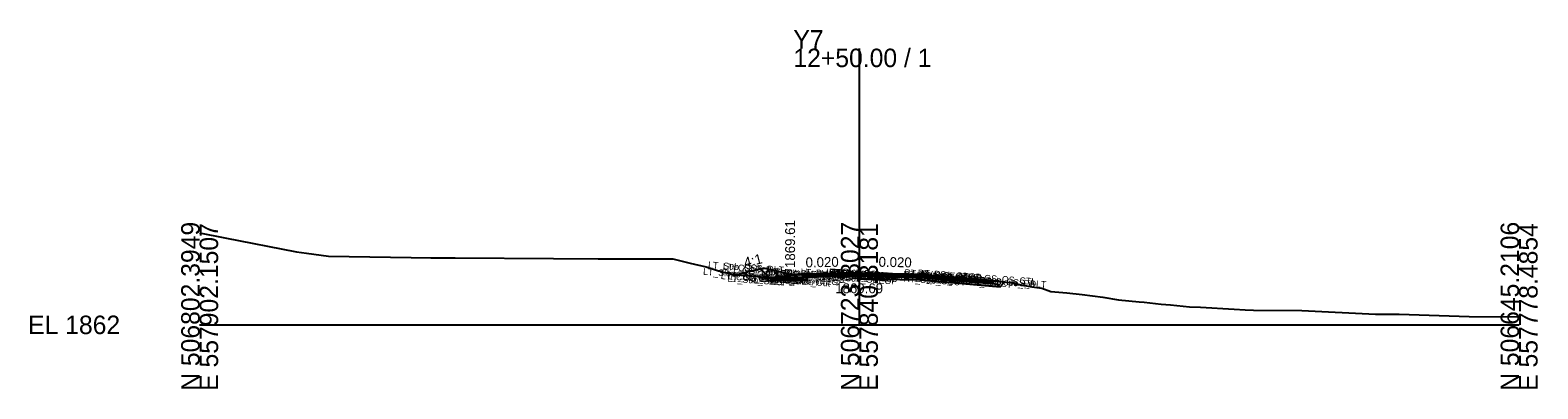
# Model space of a CAD drawing. Extents: x -26 to 557959, y -10 to 506992.
# Drawn here: x -25.7 to 202.8, y 2490.3 to 2544.6 of the extents above; entities that cross this region are included whole.
import ezdxf

# ---------------------------------------------------------------- set-up
doc = ezdxf.new("R2010")
doc.units = 0
for name, color, linetype in [('Default', 7, 'Continuous'), ('Exist CMT Pavement', 7, 'Continuous'), ('Exist Cross Section Cell', 7, 'Continuous'), ('Exist XS Center Line Elevation Label', 7, 'Continuous'), ('Exist XS Ground Line', 7, 'Continuous'), ('Prop CMT Conc Surface', 7, 'Continuous'), ('Prop CMT Concrete Structures', 7, 'Continuous'), ('Prop CMT Pvmt Course 1', 7, 'Continuous'), ('Prop CMT Pvmt Course 1 CG', 7, 'Continuous'), ('Prop CMT Pvmt Course 1 Wedge', 7, 'Continuous'), ('Prop CMT Pvmt Course 2', 7, 'Continuous'), ('Prop CMT Pvmt Course 2 Wedge', 7, 'Continuous'), ('Prop CMT Pvmt Course 3', 7, 'Continuous'), ('Prop CMT Pvmt Course 3 Wedge', 7, 'Continuous'), ('Prop CMT Pvmt Surface', 7, 'Continuous'), ('Prop CMT Pvmt Surface Shoulder', 7, 'Continuous'), ('Prop CMT Pvmt Wedge Surface 1', 7, 'Continuous'), ('Prop CMT Pvmt Wedge Surface 2', 7, 'Continuous'), ('Prop CMT Pvmt Wedge Surface 3', 7, 'Continuous'), ('Prop CMT Shld Paved Course 1', 7, 'Continuous'), ('Prop CMT Shld Paved Course 2', 7, 'Continuous'), ('Prop CMT Shld Paved Course 3', 7, 'Continuous'), ('Prop CMT Slope Grass', 7, 'Continuous'), ('Prop CMT Subgrade Earthwork', 7, 'Continuous'), ('Prop XS Earthwork Shape', 7, 'Continuous'), ('Prop XS Hydro Elevations', 7, 'Continuous'), ('Prop XS SE Text', 7, 'Continuous'), ('Prop XS Side Slope Text', 7, 'Continuous'), ('Typical Text Asphalt at Bridge Approach CELL', 7, 'Continuous')]:
    doc.layers.add(name, color=color, linetype=linetype)

msp = doc.modelspace()

# ---------------------------------------------------------------- linework, layer by layer
at = {"layer": 'Exist CMT Pavement'}
for points in [[(100, 2507.69), (92.11, 2507.72)], [(92.11, 2507.72), (96.05, 2507.71)], [(96.05, 2507.71), (100, 2507.69)]]:
    msp.add_lwpolyline(points, dxfattribs=at)
at = {"layer": 'Exist Cross Section Cell'}
for p, q in [((100, 2500), (100, 2541.84)), ((0, 2500), (100, 2500)), ((100, 2500), (200, 2500))]:
    msp.add_line(p, q, dxfattribs=at)
at = {"layer": 'Exist XS Ground Line'}
for p, q in [((0, 2513.95), (3.84, 2513.2)), ((3.84, 2513.2), (14.66, 2511.04)), ((14.66, 2511.04), (16.22, 2510.88)), ((16.22, 2510.88), (19.54, 2510.41)), ((19.54, 2510.41), (32.04, 2510.19)), ((32.04, 2510.19), (35.04, 2510.16)), ((35.04, 2510.16), (38.74, 2510.15)), ((38.74, 2510.15), (53.62, 2510.06)), ((53.62, 2510.06), (60.41, 2510.02)), ((60.41, 2510.02), (71.73, 2510.02)), ((71.73, 2510.02), (74.37, 2509.34)), ((74.37, 2509.34), (76.8, 2508.79)), ((76.8, 2508.79), (78.63, 2508.2)), ((78.63, 2508.2), (80.86, 2507.62)), ((80.86, 2507.62), (84.58, 2507.3)), ((84.58, 2507.3), (86.21, 2507.16)), ((86.21, 2507.16), (92, 2507.72)), ((92, 2507.72), (92.42, 2507.72)), ((92.42, 2507.72), (100, 2507.69)), ((100, 2507.69), (101.1, 2507.69)), ((101.1, 2507.69), (108.9, 2507.3)), ((108.9, 2507.3), (119.48, 2506.74)), ((119.48, 2506.74), (121.72, 2506.51)), ((121.72, 2506.51), (123.1, 2506.34)), ((123.1, 2506.34), (124.27, 2506.11)), ((124.27, 2506.11), (126.16, 2505.75)), ((126.16, 2505.75), (127.67, 2505.54)), ((127.67, 2505.54), (129.04, 2505.05)), ((129.04, 2505.05), (131.42, 2504.87)), ((131.42, 2504.87), (133.79, 2504.6)), ((133.79, 2504.6), (136.88, 2504.17)), ((136.88, 2504.17), (139.29, 2503.78)), ((139.29, 2503.78), (142.41, 2503.5)), ((142.41, 2503.5), (143.19, 2503.44)), ((143.19, 2503.44), (145.75, 2503.14)), ((145.75, 2503.14), (147.17, 2503.01)), ((147.17, 2503.01), (150.03, 2502.72)), ((150.03, 2502.72), (151.73, 2502.68)), ((151.73, 2502.68), (156.82, 2502.37)), ((156.82, 2502.37), (158.5, 2502.29)), ((158.5, 2502.29), (159.73, 2502.23)), ((159.73, 2502.23), (167.08, 2502.15)), ((167.08, 2502.15), (178.24, 2501.62)), ((178.24, 2501.62), (181.82, 2501.6)), ((181.82, 2501.6), (192.42, 2501.27)), ((192.42, 2501.27), (200, 2501.19))]:
    msp.add_line(p, q, dxfattribs=at)
at = {"layer": 'Prop CMT Conc Surface'}
msp.add_lwpolyline([(91.5, 2507.69), (89.5, 2507.61), (87.5, 2508.11)], dxfattribs=at)
at = {"layer": 'Prop CMT Concrete Structures'}
for points in [[(91.5, 2507.69), (89.5, 2507.61), (87.5, 2508.11)], [(87.5, 2508.11), (87.5, 2507.1)], [(87.5, 2507.1), (89.5, 2507.1), (91.5, 2507.1)], [(91.5, 2507.1), (91.5, 2507.69)]]:
    msp.add_lwpolyline(points, dxfattribs=at)
at = {"layer": 'Prop CMT Pvmt Course 1'}
for points in [[(100, 2507.86), (91.5, 2507.69)], [(91.5, 2507.69), (91.5, 2507.44)], [(91.5, 2507.44), (92.11, 2507.45)], [(92.11, 2507.58), (100, 2507.73)], [(92.11, 2507.45), (92.11, 2507.58)], [(100, 2507.61), (100, 2507.86)], [(100, 2507.61), (100, 2507.86)], [(100, 2507.86), (109.19, 2507.67)], [(100, 2507.73), (100, 2507.61), (100, 2507.61)], [(109.19, 2507.42), (100, 2507.61)], [(118.01, 2506.93), (117.99, 2506.69)]]:
    msp.add_lwpolyline(points, dxfattribs=at)
msp.add_lwpolyline([(100, 2507.61), (100, 2507.73), (100, 2507.73), (100, 2507.61)], close=True, dxfattribs=at)
at = {"layer": 'Prop CMT Pvmt Course 1 CG'}
for points in [[(91.5, 2507.1), (87, 2507.1), (86.7, 2506.81)], [(91.5, 2506.81), (91.5, 2507.1)], [(86.7, 2506.81), (91.5, 2506.81)]]:
    msp.add_lwpolyline(points, dxfattribs=at)
at = {"layer": 'Prop CMT Pvmt Course 1 Wedge'}
msp.add_lwpolyline([(100, 2507.73), (92.11, 2507.58)], dxfattribs=at)
at = {"layer": 'Prop CMT Pvmt Course 2'}
for points in [[(92.11, 2507.45), (91.5, 2507.44)], [(91.5, 2507.44), (91.5, 2507.19)], [(91.5, 2507.19), (92.11, 2507.2)], [(92.11, 2507.2), (92.11, 2507.45)], [(100, 2507.36), (100, 2507.61)], [(100, 2507.61), (109.19, 2507.42)], [(109.19, 2507.17), (100, 2507.36)], [(117.99, 2506.69), (117.97, 2506.44)]]:
    msp.add_lwpolyline(points, dxfattribs=at)
at = {"layer": 'Prop CMT Pvmt Course 2 Wedge'}
msp.add_lwpolyline([(100, 2507.61), (92.11, 2507.45)], dxfattribs=at)
at = {"layer": 'Prop CMT Pvmt Course 3'}
for points in [[(92.11, 2507.2), (91.5, 2507.19)], [(91.5, 2507.19), (91.5, 2506.81)], [(92.11, 2506.83), (92.11, 2507.2)], [(100, 2506.98), (100, 2507.36)], [(100, 2507.36), (109.19, 2507.17)], [(91.5, 2506.81), (92.11, 2506.83)], [(109.19, 2506.8), (100, 2506.98)], [(117.97, 2506.44), (117.95, 2506.06)]]:
    msp.add_lwpolyline(points, dxfattribs=at)
at = {"layer": 'Prop CMT Pvmt Course 3 Wedge'}
msp.add_lwpolyline([(100, 2507.36), (92.11, 2507.2)], dxfattribs=at)
at = {"layer": 'Prop CMT Pvmt Surface'}
for points in [[(100, 2507.86), (91.5, 2507.69)], [(100, 2507.86), (109.19, 2507.67), (120, 2506.77)]]:
    msp.add_lwpolyline(points, dxfattribs=at)
at = {"layer": 'Prop CMT Pvmt Surface Shoulder'}
msp.add_lwpolyline([(91.5, 2507.69), (91.5, 2507.69)], dxfattribs=at)
at = {"layer": 'Prop CMT Pvmt Wedge Surface 1'}
for points in [[(91.5, 2507.44), (91.5, 2507.69)], [(92.11, 2507.45), (91.5, 2507.44)], [(100, 2507.73), (92.11, 2507.58)], [(92.11, 2507.58), (92.11, 2507.45)]]:
    msp.add_lwpolyline(points, dxfattribs=at)
at = {"layer": 'Prop CMT Pvmt Wedge Surface 2'}
for points in [[(91.5, 2507.44), (91.5, 2507.69)], [(100, 2507.61), (91.5, 2507.44)]]:
    msp.add_lwpolyline(points, dxfattribs=at)
at = {"layer": 'Prop CMT Pvmt Wedge Surface 3'}
for points in [[(91.5, 2507.19), (91.5, 2507.69)], [(100, 2507.36), (91.5, 2507.19)]]:
    msp.add_lwpolyline(points, dxfattribs=at)
at = {"layer": 'Prop CMT Shld Paved Course 1'}
for points in [[(91.5, 2507.69), (91.5, 2507.69), (91.5, 2507.44), (91.5, 2507.44)], [(91.5, 2507.44), (91.5, 2507.69)], [(109.19, 2507.67), (120, 2506.77), (120.24, 2506.5)], [(120.24, 2506.5), (109.19, 2507.42)], [(117.99, 2506.69), (118.01, 2506.93)]]:
    msp.add_lwpolyline(points, dxfattribs=at)
at = {"layer": 'Prop CMT Shld Paved Course 2'}
for points in [[(91.5, 2507.44), (91.5, 2507.44), (91.5, 2507.19), (91.5, 2507.19)], [(91.5, 2507.19), (91.5, 2507.44)], [(109.19, 2507.42), (120.24, 2506.5), (120.48, 2506.23)], [(120.48, 2506.23), (109.19, 2507.17)], [(117.97, 2506.44), (117.99, 2506.69)]]:
    msp.add_lwpolyline(points, dxfattribs=at)
at = {"layer": 'Prop CMT Shld Paved Course 3'}
for points in [[(91.5, 2507.19), (91.5, 2507.19), (91.5, 2506.81), (91.5, 2506.81)], [(91.5, 2506.81), (91.5, 2507.19)], [(109.19, 2507.17), (120.48, 2506.23), (120.98, 2506.18), (121.33, 2505.78)], [(121.33, 2505.78), (109.19, 2506.8)], [(117.95, 2506.06), (117.97, 2506.44)]]:
    msp.add_lwpolyline(points, dxfattribs=at)
at = {"layer": 'Prop CMT Slope Grass'}
for points in [[(87.5, 2508.11), (85.5, 2508.61), (81.37, 2507.58)], [(120, 2506.77), (121.99, 2506.48)]]:
    msp.add_lwpolyline(points, dxfattribs=at)
at = {"layer": 'Prop CMT Subgrade Earthwork'}
for p, q in [((100, 2506.98), (100, 2507.69)), ((121.33, 2505.78), (121.99, 2506.48))]:
    msp.add_line(p, q, dxfattribs=at)
for points in [[(91.5, 2506.81), (86.7, 2506.81), (85.03, 2508.49)], [(92.11, 2506.83), (92.12, 2507.72)], [(92.11, 2506.83), (91.5, 2506.81)], [(91.5, 2506.81), (91.5, 2506.81)], [(100, 2506.98), (109.19, 2506.8)], [(109.19, 2506.8), (121.33, 2505.78)]]:
    msp.add_lwpolyline(points, dxfattribs=at)
at = {"layer": 'Prop XS Earthwork Shape'}
for points in [[(86.34, 2507.18), (85.03, 2508.49), (81.37, 2507.58), (84.58, 2507.3), (86.21, 2507.16)], [(86.34, 2507.18), (91.84, 2507.71), (92.12, 2507.72), (92.11, 2506.83), (91.5, 2506.81), (86.7, 2506.81)], [(92, 2507.72), (92.12, 2507.72), (91.84, 2507.71)], [(121.33, 2505.78), (121.99, 2506.48), (121.72, 2506.51), (119.48, 2506.74), (108.9, 2507.3), (101.1, 2507.69), (100, 2507.69), (100, 2506.98), (109.19, 2506.8)]]:
    msp.add_lwpolyline(points, close=True, dxfattribs=at)

# ---------------------------------------------------------------- texts
at = {"layer": 'Default'}
msp.add_text('-', height=0.0001, dxfattribs=at).set_placement((0, 2500))
at = {"layer": 'Exist Cross Section Cell'}
for s, p in [('Y7', (90, 2541.84)), ('12+50.00 / 1', (90, 2539.04)), ('EL 1862', (-26, 2498.6))]:
    msp.add_text(s, height=2.8, dxfattribs=at).set_placement(p)
for s, p in [('N 506802.3949', (0, 2490)), ('E 557902.1507', (2.8, 2490)), ('N 506723.8027', (100, 2490)), ('E 557840.3181', (102.8, 2490)), ('N 506645.2106', (200, 2490)), ('E 557778.4854', (202.8, 2490))]:
    msp.add_text(s, height=2.8, rotation=90, dxfattribs=at).set_placement(p)
at = {"layer": 'Exist XS Center Line Elevation Label'}
msp.add_text('1869.69', height=1.5, dxfattribs=at).set_placement((96.34, 2504.79))
at = {"layer": 'Prop XS Hydro Elevations'}
msp.add_text('1869.61', height=1.5, rotation=90, dxfattribs=at).set_placement((90.25, 2508.61))
at = {"layer": 'Prop XS SE Text'}
for rotation, p in [(1.1458, (91.86, 2508.7)), (358.8542, (102.9, 2508.8))]:
    msp.add_text('0.020', height=1.5, rotation=rotation, dxfattribs=at).set_placement(p)
at = {"layer": 'Prop XS Side Slope Text'}
msp.add_text('4:1', height=1.5, rotation=14.0362, dxfattribs=at).set_placement((82.7, 2508.68))
at = {"layer": 'Typical Text Asphalt at Bridge Approach CELL'}
for s, p in [('LT_Sub_OSS_DLT', (77.04, 2508.61)), ('LT_CSLP_Pnt', (79.27, 2508.32)), ('LT_Slope_Fill', (76.28, 2507.59)), ('LT_CG1_Shelf_Out', (78.97, 2506.94)), ('LT_CG_Top_BOC', (79.88, 2507.92)), ('LT_Sub_OEOP', (79.95, 2506.56)), ('LT_CG_Bot_BOC', (80.02, 2506.9)), ('LT_CG_Top_Gut', (82.16, 2507.4)), ('LT_CG_Bot_Gut', (82.3, 2506.88)), ('LT_Sub_Trench_Out', (83.09, 2506.68)), ('LT_PV2_OEOT', (84.72, 2507.19)), ('LT_PV3_OEOT', (84.72, 2506.94)), ('LT_Sub_OEOT', (84.74, 2506.56)), ('LT_PS2_OEOP', (84.76, 2507.18)), ('LT_PS3_OEOP', (84.76, 2506.93)), ('LT_PV1_OEOT', (84.84, 2507.43)), ('LT_PS1_OEOP', (84.88, 2507.42)), ('LT_CG_Bot_IE', (84.89, 2506.84)), ('LT_PV_Sub_Tie_Out', (86.27, 2507.63)), ('LT_PV_OEEOP_EG', (86.68, 2507.6)), ('LT_PV2_OEEOP', (87.48, 2507.27)), ('LT_PV3_OEEOP', (87.48, 2507.02)), ('LT_Sub_OEEOP', (87.5, 2506.65)), ('LT_PV1_OEEOP', (87.6, 2507.39)), ('LT_PV_EG_TestPt', (91.07, 2507.55)), ('LT_PV_IEEOP_EG', (94.96, 2507.54)), ('RT_PV2_OEEOP', (95.31, 2507.43)), ('RT_PV3_OEEOP', (95.31, 2507.18)), ('RT_Sub_OEEOP', (95.33, 2506.81)), ('RT_PV1_OEEOP', (95.43, 2507.55)), ('RT_PV2_IEEOP', (95.69, 2507.41)), ('LT_PV2_IEEOP', (95.75, 2507.4)), ('LT_PV3_IEEOP', (95.75, 2507.15)), ('RT_PV1_IEEOP', (95.81, 2507.52)), ('LT_PV1_IEEOP', (95.87, 2507.52)), ('PV2_PGL', (97.32, 2507.29)), ('PV1_PGL', (97.44, 2507.54)), ('RT_PV2_OEOT', (106.66, 2507.19)), ('RT_PV3_OEOT', (106.66, 2506.94)), ('RT_Sub_OEOT', (106.69, 2506.56)), ('RT_PV1_OEOT', (106.78, 2507.43)), ('RT_Sub_Trench_Out', (108.42, 2506.61)), ('RT_PS3_Shelf_Out', (108.59, 2506.96)), ('RT_PS1_OEOP', (108.82, 2507.39)), ('RT_PS2_OEOP', (108.96, 2507.14)), ('RT_PS3_OEOP', (109.21, 2506.89)), ('RT_GS_OS_CTL', (116.38, 2506.78)), ('RT_Sub_OSS_DLT', (116.59, 2506.41)), ('RT_Slope_Fill', (118.12, 2506.24))]:
    msp.add_text(s, height=1, rotation=356, dxfattribs=at).set_placement(p)

doc.saveas('drawing.dxf')
